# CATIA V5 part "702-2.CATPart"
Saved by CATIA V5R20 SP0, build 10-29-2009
Part number: 702-2
Source: Unknown
Property "ARTICLENO": "702-2"
Property "BOMINFO": "702-2"
Property "CODE": "702-2"
Property "L": "65.000"
Property "LINA": "702-2"
Property "NB": "702-2"
Property "NBSYN": "$CODE."
Property "NN": "702"
Property "SUPPLIER": "CF"
Bounding box of the stored display mesh (mm): x -107 to 0, y 0 to 65, z -15 to 15
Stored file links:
  C:\Users\Utente\Desktop\3D files 702\702-2.CATPart
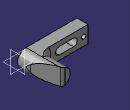
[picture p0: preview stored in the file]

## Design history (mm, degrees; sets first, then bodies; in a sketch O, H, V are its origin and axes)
Body1 "Geometry.1" (main body)
  Solid1 "702-2.catpart": solid without history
